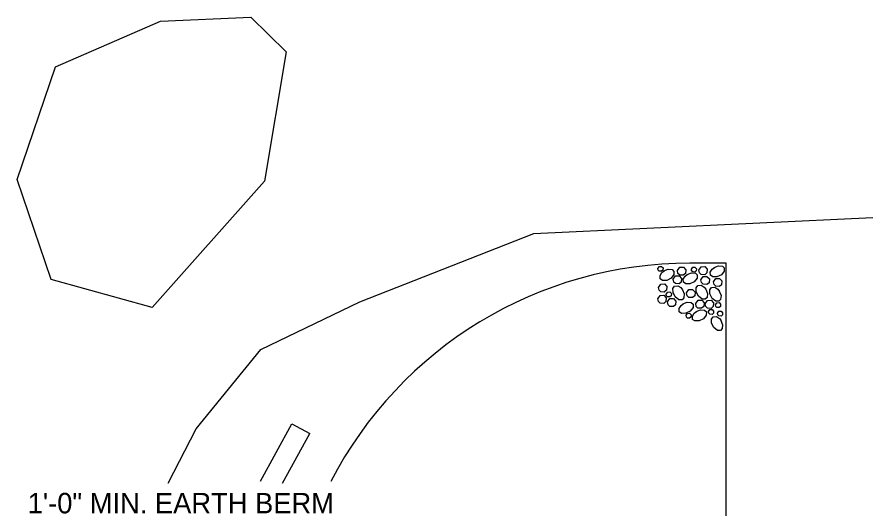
# Model space of a CAD drawing. Extents: x 985 to 1514, y -701 to -21.
# Drawn here: x 1133.4 to 1175.3, y -136.79 to -112.74 of the extents above; entities that cross this region are included whole.
import ezdxf

# ---------------------------------------------------------------- set-up
doc = ezdxf.new("R2010")
doc.units = 0
for name, color, linetype in [('Exist Hydro Stream or Body of Water', 7, 'Continuous'), ('Exist Structure Major Bridge Seam', 7, 'Continuous'), ('Miscellaneous Lines CELL', 7, 'Continuous'), ('Sup Concrete Girder Lines', 7, 'Continuous'), ('Text', 7, 'Continuous')]:
    doc.layers.add(name, color=color, linetype=linetype)

msp = doc.modelspace()

# ---------------------------------------------------------------- linework, layer by layer
at = {"layer": 'Exist Hydro Stream or Body of Water'}
for points in [[(1140.424, -112.944), (1144.845, -112.742), (1146.573, -114.431), (1145.507, -120.766), (1140.012, -126.94), (1135.059, -125.576), (1133.399, -120.683), (1135.271, -115.173), (1140.424, -112.944)], [(1140.8, -135.528), (1142.162, -132.882), (1145.33, -129.003), (1150.185, -126.673), (1158.708, -123.316), (1175.303, -122.544)]]:
    msp.add_lwpolyline(points, dxfattribs=at)
at = {"layer": 'Exist Structure Major Bridge Seam'}
for p, q in [((1145.317, -135.431), (1146.855, -132.626)), ((1146.855, -132.626), (1147.732, -133.107)), ((1146.398, -135.538), (1147.732, -133.107))]:
    msp.add_line(p, q, dxfattribs=at)
at = {"layer": 'Miscellaneous Lines CELL'}
for points in [[(1164.779, -125.033), (1164.846, -124.938), (1164.953, -124.931), (1165.028, -125.009), (1165.017, -125.117), (1164.951, -125.172), (1164.845, -125.165), (1164.795, -125.116), (1164.779, -125.033)], [(1165.069, -125.156), (1165.279, -125.073), (1165.471, -125.09), (1165.563, -125.177), (1165.56, -125.333), (1165.421, -125.51), (1165.206, -125.618), (1165.004, -125.621), (1164.89, -125.54), (1164.879, -125.379), (1164.972, -125.235), (1165.077, -125.151)], [(1165.733, -125.136), (1165.845, -124.976), (1166.024, -124.966), (1166.148, -125.095), (1166.13, -125.276), (1166.02, -125.368), (1165.843, -125.355), (1165.76, -125.274), (1165.733, -125.136)], [(1166.208, -125.325), (1166.417, -125.242), (1166.61, -125.259), (1166.701, -125.346), (1166.698, -125.502), (1166.559, -125.68), (1166.345, -125.787), (1166.143, -125.791), (1166.029, -125.71), (1166.018, -125.549), (1166.11, -125.404), (1166.216, -125.32)], [(1166.413, -125.07), (1166.48, -124.974), (1166.587, -124.968), (1166.662, -125.046), (1166.651, -125.154), (1166.585, -125.209), (1166.479, -125.202), (1166.429, -125.153), (1166.413, -125.07)], [(1166.78, -125.111), (1166.892, -124.952), (1167.071, -124.942), (1167.195, -125.071), (1167.177, -125.251), (1167.067, -125.343), (1166.89, -125.331), (1166.807, -125.25), (1166.78, -125.111)], [(1167.532, -124.984), (1167.741, -124.901), (1167.934, -124.917), (1168.025, -125.004), (1168.022, -125.161), (1167.884, -125.338), (1167.669, -125.446), (1167.467, -125.449), (1167.353, -125.368), (1167.342, -125.207), (1167.434, -125.063), (1167.54, -124.979)], [(1165.522, -125.557), (1165.634, -125.398), (1165.813, -125.388), (1165.937, -125.517), (1165.919, -125.697), (1165.809, -125.789), (1165.632, -125.776), (1165.549, -125.696), (1165.522, -125.557)], [(1166.885, -125.589), (1166.997, -125.429), (1167.176, -125.419), (1167.301, -125.548), (1167.283, -125.729), (1167.172, -125.82), (1166.995, -125.808), (1166.912, -125.727), (1166.885, -125.589)], [(1167.498, -125.686), (1167.61, -125.527), (1167.789, -125.517), (1167.913, -125.645), (1167.895, -125.826), (1167.785, -125.918), (1167.608, -125.905), (1167.525, -125.825), (1167.498, -125.686)], [(1164.803, -125.957), (1164.915, -125.798), (1165.094, -125.788), (1165.219, -125.917), (1165.201, -126.097), (1165.09, -126.189), (1164.914, -126.176), (1164.83, -126.096), (1164.804, -125.957)], [(1165.98, -126.07), (1166.063, -126.279), (1166.046, -126.472), (1165.959, -126.563), (1165.803, -126.56), (1165.625, -126.422), (1165.518, -126.207), (1165.514, -126.005), (1165.595, -125.891), (1165.756, -125.88), (1165.901, -125.972), (1165.985, -126.078)], [(1166.181, -126.228), (1166.293, -126.069), (1166.472, -126.059), (1166.596, -126.188), (1166.578, -126.368), (1166.468, -126.46), (1166.291, -126.447), (1166.208, -126.367), (1166.181, -126.228)], [(1167.118, -126.043), (1167.201, -126.252), (1167.185, -126.445), (1167.098, -126.536), (1166.942, -126.533), (1166.764, -126.394), (1166.657, -126.18), (1166.653, -125.977), (1166.734, -125.864), (1166.895, -125.853), (1167.039, -125.945), (1167.124, -126.051)], [(1167.783, -126.144), (1167.866, -126.354), (1167.849, -126.546), (1167.762, -126.638), (1167.606, -126.635), (1167.428, -126.496), (1167.321, -126.281), (1167.317, -126.079), (1167.398, -125.965), (1167.56, -125.955), (1167.704, -126.047), (1167.788, -126.153)], [(1164.772, -126.511), (1164.884, -126.351), (1165.063, -126.341), (1165.187, -126.47), (1165.169, -126.651), (1165.059, -126.743), (1164.882, -126.73), (1164.799, -126.649), (1164.772, -126.511)], [(1165.188, -126.284), (1165.256, -126.188), (1165.363, -126.182), (1165.438, -126.259), (1165.427, -126.368), (1165.36, -126.423), (1165.254, -126.415), (1165.205, -126.367), (1165.188, -126.284)], [(1165.245, -126.669), (1165.358, -126.509), (1165.536, -126.499), (1165.661, -126.628), (1165.643, -126.809), (1165.532, -126.901), (1165.356, -126.888), (1165.273, -126.807), (1165.246, -126.669)], [(1166.004, -126.762), (1166.214, -126.679), (1166.406, -126.696), (1166.498, -126.783), (1166.495, -126.939), (1166.356, -127.117), (1166.142, -127.224), (1165.939, -127.228), (1165.825, -127.147), (1165.815, -126.986), (1165.907, -126.841), (1166.013, -126.757)], [(1166.629, -126.748), (1166.741, -126.588), (1166.92, -126.578), (1167.045, -126.707), (1167.027, -126.888), (1166.916, -126.98), (1166.739, -126.967), (1166.656, -126.886), (1166.629, -126.748)], [(1167.09, -126.755), (1167.202, -126.595), (1167.381, -126.585), (1167.506, -126.714), (1167.488, -126.895), (1167.377, -126.987), (1167.2, -126.974), (1167.117, -126.893), (1167.09, -126.755)], [(1167.6, -126.804), (1167.667, -126.708), (1167.775, -126.702), (1167.849, -126.779), (1167.838, -126.888), (1167.772, -126.943), (1167.666, -126.935), (1167.616, -126.887), (1167.6, -126.804)], [(1166.155, -127.324), (1166.222, -127.228), (1166.33, -127.222), (1166.404, -127.3), (1166.394, -127.408), (1166.327, -127.463), (1166.221, -127.456), (1166.171, -127.407), (1166.155, -127.324)], [(1166.655, -127.137), (1166.864, -127.054), (1167.057, -127.07), (1167.148, -127.157), (1167.145, -127.314), (1167.006, -127.491), (1166.792, -127.599), (1166.59, -127.602), (1166.476, -127.521), (1166.465, -127.36), (1166.557, -127.216), (1166.663, -127.132)], [(1167.253, -127.14), (1167.32, -127.044), (1167.428, -127.038), (1167.502, -127.116), (1167.492, -127.224), (1167.425, -127.279), (1167.319, -127.272), (1167.269, -127.223), (1167.253, -127.14)], [(1167.864, -127.574), (1167.947, -127.784), (1167.93, -127.977), (1167.843, -128.068), (1167.687, -128.065), (1167.51, -127.926), (1167.402, -127.712), (1167.399, -127.509), (1167.48, -127.396), (1167.641, -127.385), (1167.785, -127.477), (1167.869, -127.583)], [(1167.695, -127.219), (1167.762, -127.123), (1167.869, -127.117), (1167.944, -127.195), (1167.933, -127.303), (1167.867, -127.358), (1167.761, -127.35), (1167.711, -127.302), (1167.695, -127.219)]]:
    msp.add_lwpolyline(points, dxfattribs=at)
at = {"layer": 'Sup Concrete Girder Lines'}
for p, q in [((1168.122, -124.768), (1166.343, -124.775)), ((1168.122, -140.593), (1168.122, -124.768))]:
    msp.add_line(p, q, dxfattribs=at)
msp.add_arc((1166.327, -144.57), 19.795, 89.9534, 152.5621, dxfattribs=at)

# ---------------------------------------------------------------- texts
at = {"layer": 'Text'}
msp.add_text('1\'-0" MIN. EARTH BERM', height=1, dxfattribs=at).set_placement((1133.918, -137.01))

doc.saveas('drawing.dxf')
